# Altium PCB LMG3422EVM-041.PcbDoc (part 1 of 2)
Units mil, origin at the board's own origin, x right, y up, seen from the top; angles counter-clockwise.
Board outline 3001 x 1535.46 mil, 4 copper layers (Top Layer, MidLayer1, MidLayer2, Bottom Layer), stack 46.2 mil thick; 103 components, 73 nets, 350 pads, 858 vias.
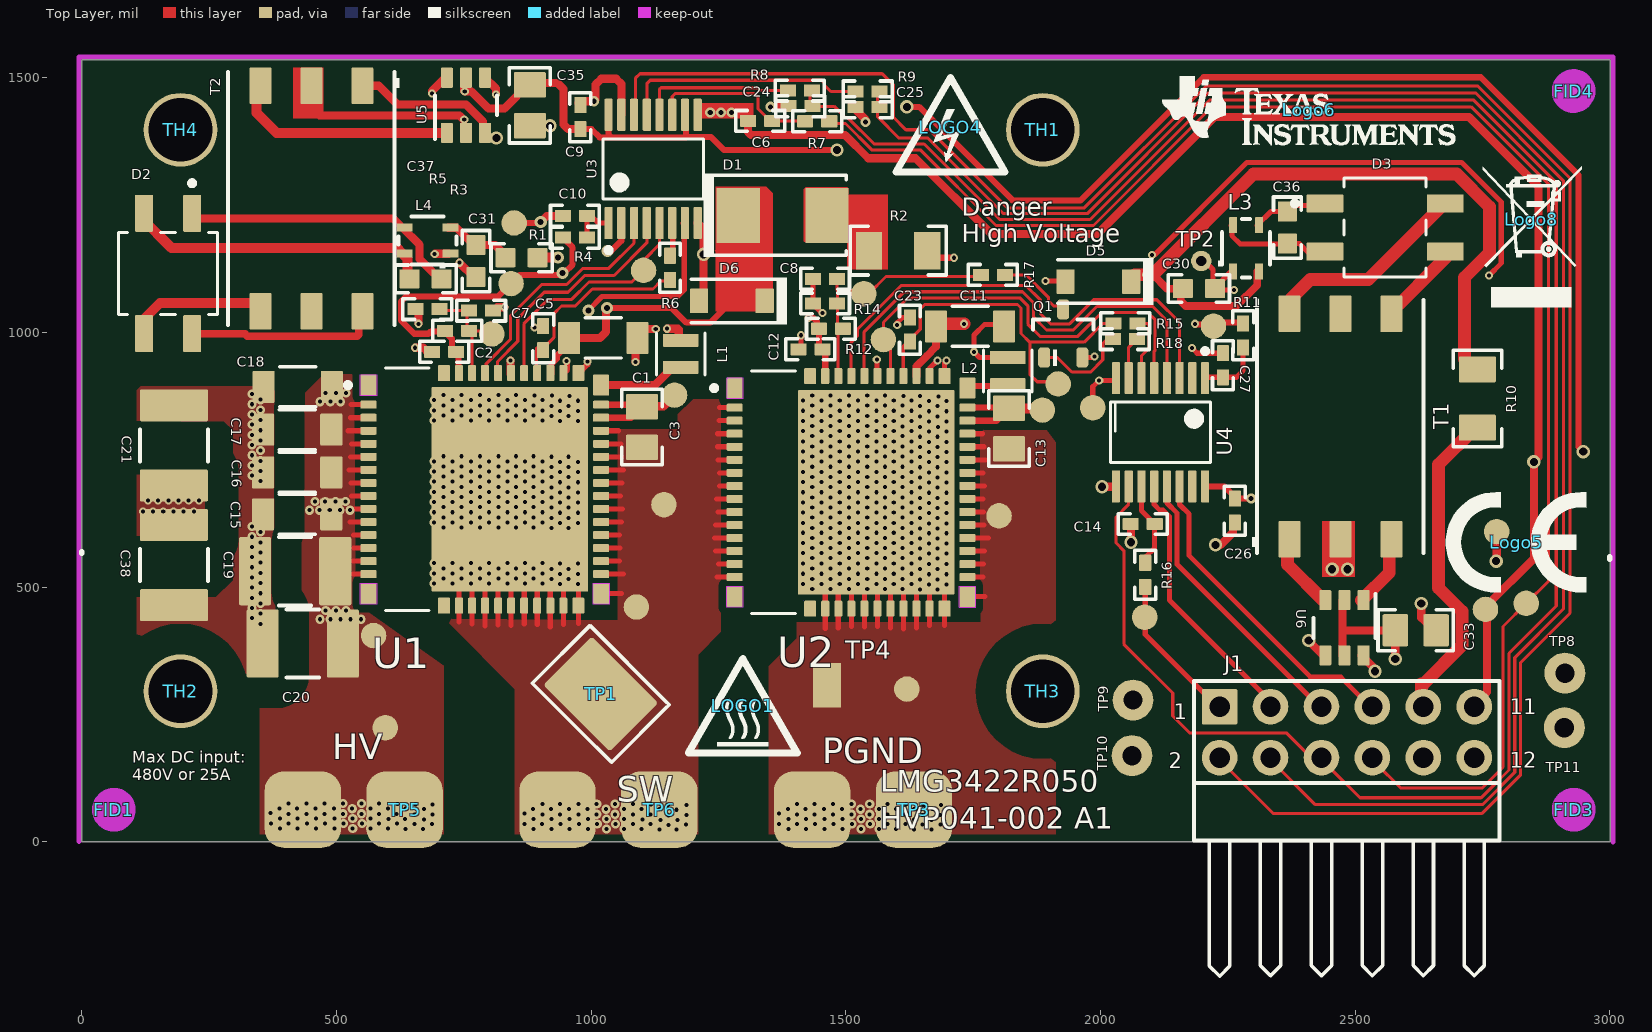
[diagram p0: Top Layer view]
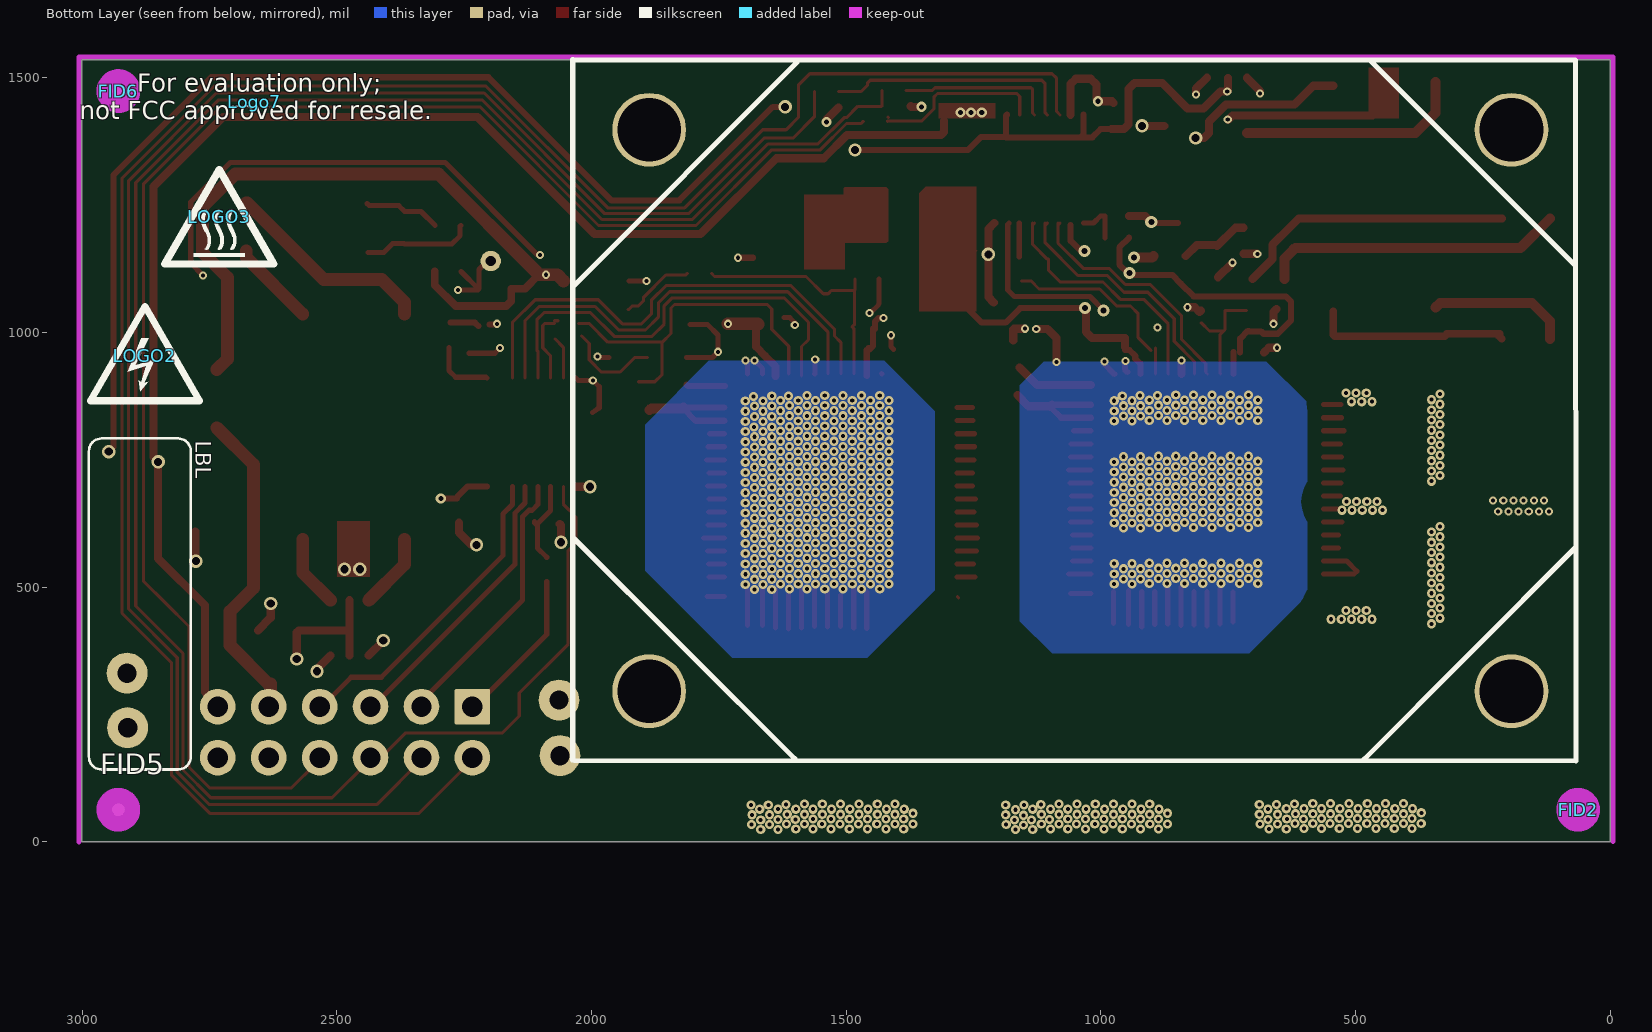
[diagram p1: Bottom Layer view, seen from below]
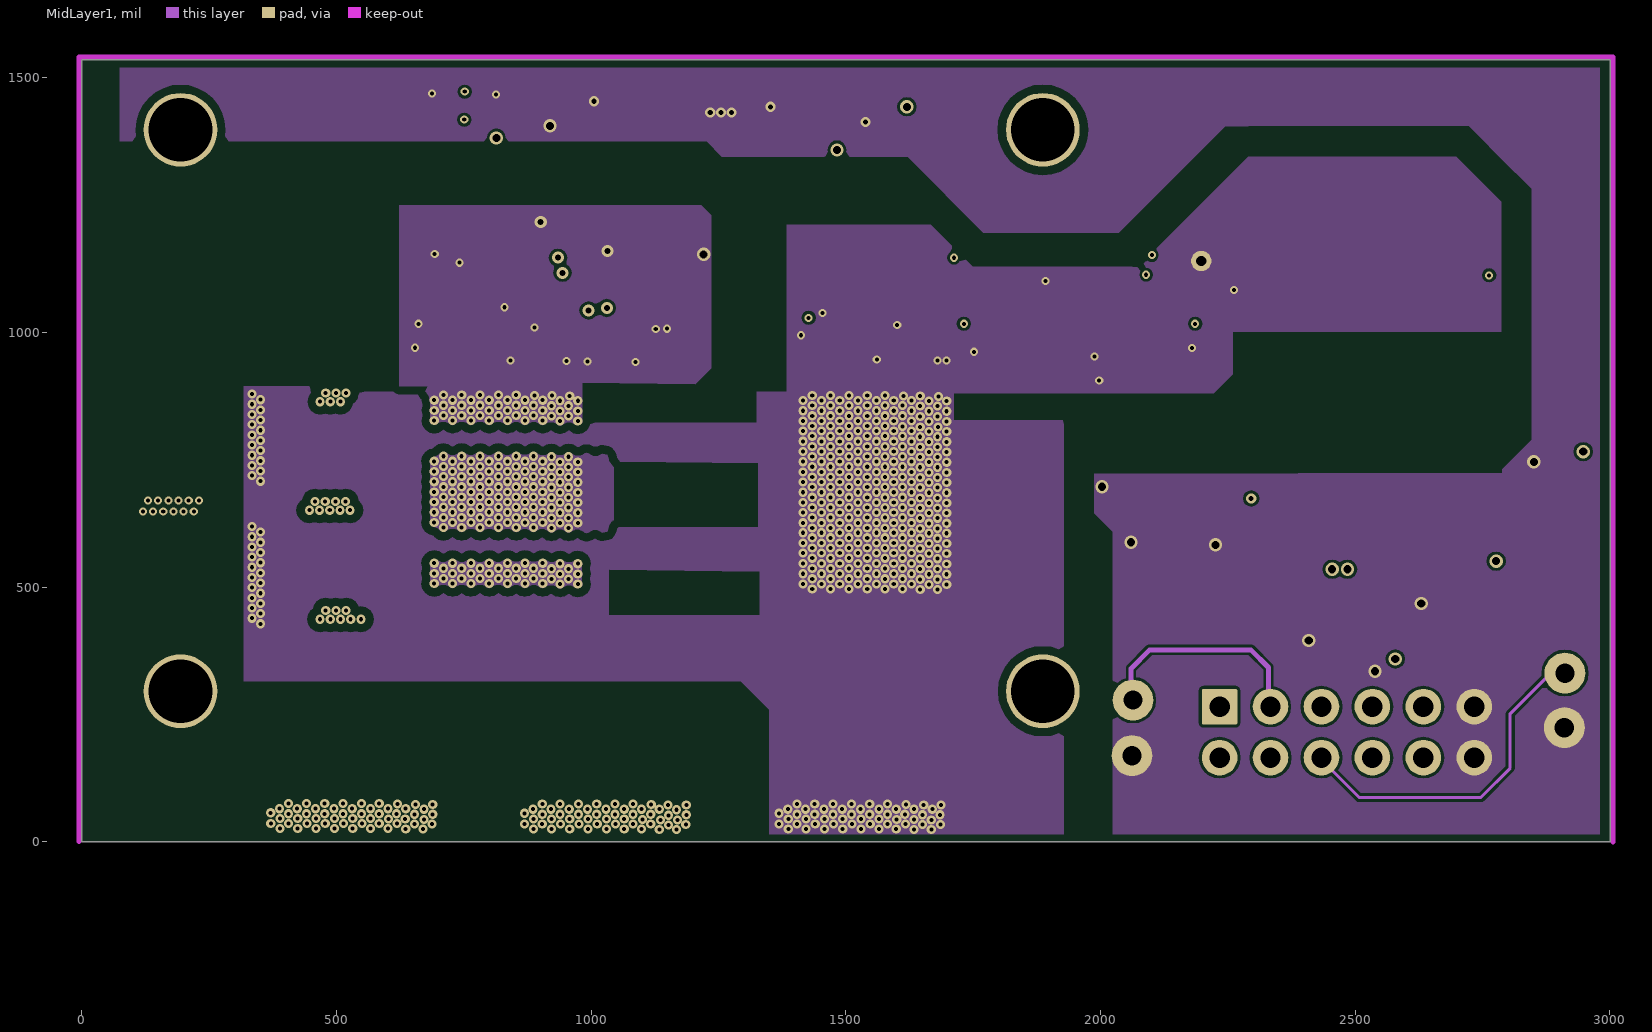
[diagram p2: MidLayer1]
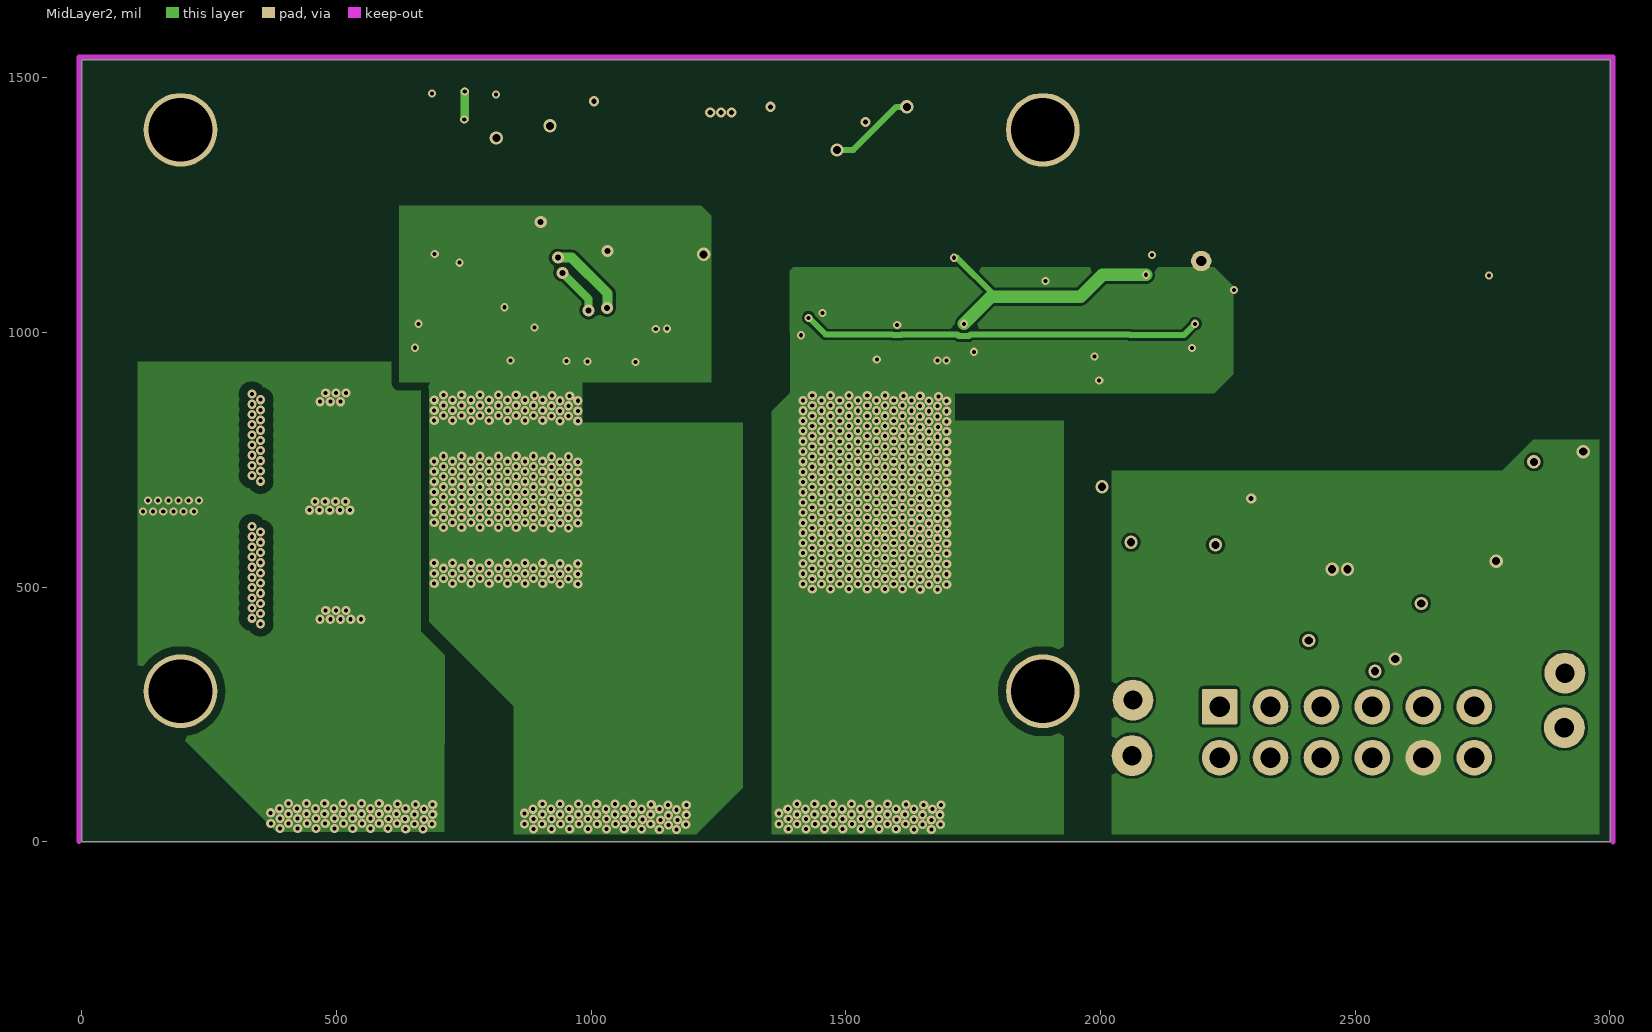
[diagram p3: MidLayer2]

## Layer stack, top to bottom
Top Solder: solder mask 0.4, Solder Resist, Dk 3.5
Top Layer: signal copper 2.8
Dielectric1: core 4.6, FR-4 High Tg, Dk 4.8
MidLayer1: signal copper 2.8
Dielectric2: prepreg 25.8, FR-4 High Tg, Dk 4.8
MidLayer2: signal copper 2.8
Dielectric3: core 4.6, FR-4 High Tg, Dk 4.8
Bottom Layer: signal copper 2.8
Bottom Solder: solder mask 0.4, Solder Resist, Dk 3.5

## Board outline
0,1535.46 3001,1535.46 3001,0 0,0
cut-out: 30,1685

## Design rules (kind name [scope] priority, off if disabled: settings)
AcuteAngle [All] p1: minimum=4.50000000000000E+0001 checktracksonly=FALSE
AssemblyTestPointUsage [All] p1: valid=2
BoardOutlineClearance [OnCopper] p1: gap=15 ignorepadtopadclearanceinfootprint=FALSE
Clearance Clearance_1 [Keepout vs InNet('SW') or InNet('HVBUS') or InNet('PGND')] p1: gap=16 ignorepadtopadclearanceinfootprint=FALSE
Clearance Clearance_VSW_Mid1 [(OnMultiLayer Or OnMid) And InNetClass('VSWNET') vs OnMid And Not InNetClass('VSWNET')] p2: gap=16 ignorepadtopadclearanceinfootprint=TRUE
Clearance Clearance_VSW_Mid2 [(OnMultiLayer Or OnMid) And Not InNetClass('VSWNET') vs OnMid And InNetClass('VSWNET')] p3: gap=16 ignorepadtopadclearanceinfootprint=TRUE
Clearance Clearance_VSW [InNetClass('VSWNET')   and OnCopper vs Not InNetClass('VSWNET')     and OnCopper] p4: gap=60 ignorepadtopadclearanceinfootprint=TRUE
Clearance Clearance_VHV_Mid1 [(OnMultiLayer Or OnMid) And InNetClass('VHV') vs OnMid And Not InNetClass('VHV')] p5: gap=16 ignorepadtopadclearanceinfootprint=TRUE
Clearance Clearance_VHV_Mid2 [(OnMultiLayer Or OnMid) And Not InNetClass('VHV') vs OnMid And InNetClass('VHV')] p6: gap=16 ignorepadtopadclearanceinfootprint=TRUE
Clearance Clearance_VHV [InNetClass('VHV') vs Not InNetClass('VHV')] p7: gap=60 ignorepadtopadclearanceinfootprint=FALSE
Clearance Clearance_INGND [InNetClass('INGND') and OnCopper vs Not InNetClass('INGND')  and OnCopper] p8: gap=60 ignorepadtopadclearanceinfootprint=FALSE
Clearance [All] p9: gap=5.5 ignorepadtopadclearanceinfootprint=FALSE
ComponentClearance ComponentClearance_Shunt [InComponentClass('Header') vs InComponentClass('Shunt')] p1 off: gap=0 collisioncheckmode=3 verticalgap=0 showdistances=FALSE
ComponentClearance ComponentClearance_MountingHoles_FiducialMarks [InComponentClass('Mounting Holes') vs InComponentClass('FiducialMark')] p2 off: gap=50 collisioncheckmode=3 verticalgap=10 showdistances=FALSE
ComponentClearance ComponentClearance_Logo [InComponentClass('Logo')] p3 off: gap=0 collisioncheckmode=3 verticalgap=10 showdistances=FALSE
ComponentClearance ComponentClearance_ScrewToNut [(HasFootprint('NY PMS 440 0025 PH')) vs (HasFootprint('Keystone_1902C'))] p4 off: gap=5 collisioncheckmode=3 verticalgap=10 showdistances=FALSE
ComponentClearance ComponentClearance_MountingHoles [InComponentClass('Mounting Holes')] p5 off: gap=250 collisioncheckmode=3 verticalgap=100000 showdistances=FALSE
ComponentClearance ComponentClearance_SmallPassives [HasFootprint('0201*') or HasFootprint('0402*') or HasFootprint('0508') or HasFootprint('0603*') or HasFootprint('0612') or HasFootprint('0805*') or HasFootprint('0815*') or HasFootprint('0830*') or HasFootprint('1206*') or HasFootprint('1210*') or HasFootprint('1808*') or HasFootprint('1812*') or HasFootprint('1825*') or HasFootprint('2010*') or HasFootprint('2220*') or HasFootprint('2225*') or HasFootprint('2512*') or HasFootprint('2728*') or HasFootprint('3518*') vs HasFootprint('0201*') or HasFootprint('0402*') or HasFootprint('0508') or HasFootprint('0603*') or HasFootprint('0612') or HasFootprint('0805*') or HasFootprint('0815*') or HasFootprint('0830*') or HasFootprint('1206*') or HasFootprint('1210*') or HasFootprint('1808*') or HasFootprint('1812*') or HasFootprint('1825*') or HasFootprint('2010*') or HasFootprint('2220*') or HasFootprint('2225*') or HasFootprint('2512*') or HasFootprint('2728*') or HasFootprint('3518*')] p6 off: gap=15 collisioncheckmode=3 verticalgap=10 showdistances=FALSE
ComponentClearance ComponentClearance_THtoSMT [IsThruComponent vs IsSMTComponent] p7 off: gap=30 collisioncheckmode=3 verticalgap=30 showdistances=FALSE
ComponentClearance ComponentClearance_THtoTH [IsThruComponent vs IsThruComponent] p8 off: gap=74 collisioncheckmode=3 verticalgap=30 showdistances=FALSE
ComponentClearance [All] p9 off: gap=15 collisioncheckmode=3 verticalgap=10 showdistances=FALSE
DiffPairsRouting [All] p1: maxlimit=100 minlimit=10 mostfreqgap=10 toplayer_minwidth=15 toplayer_maxwidth=15 toplayer_prefwidth=15 midlayer1_minwidth=15 midlayer1_maxwidth=15 midlayer1_prefwidth=15 midlayer2_minwidth=15 midlayer2_maxwidth=15 midlayer2_prefwidth=15 bottomlayer_minwidth=15 bottomlayer_maxwidth=15 bottomlayer_prefwidth=15 maxuncoupledlength=1000
FabricationTestPointUsage TestPointUsage [All] p1: valid=2 allowmultiple=FALSE
FabricationTestpoint Testpoint [All] p1: side=3 testpointundercomponent=TRUE minsize=40 maxsize=100 preferedsize=60 minholesize=0 maxholesize=40 preferedholesize=32 testpointgrid=1 allowsidetop=TRUE allowsidebottom=TRUE usegrid=TRUE gridtolerance=0.01
FanoutControl Fanout_LCC [IsLCC] p1: bgadir=Out bgaviamode=Centered fanoutstyle=Auto fanoutdirection=Alternating viagrid=1 // Fanout_LCC (Default Rule)
FanoutControl Fanout_BGA [IsBGA] p2: bgadir=Out bgaviamode=Centered fanoutstyle=Auto fanoutdirection=Alternating viagrid=1 // Fanout_BGA (Default Rule)
FanoutControl Fanout_Default [All] p4: bgadir=Out bgaviamode=Centered fanoutstyle=Auto fanoutdirection=Alternating viagrid=1 // Fanout_Default (Default Rule)
FanoutControl Fanout_Small [(CompPinCount < 5)] p5: bgadir=Out bgaviamode=Centered fanoutstyle=Auto fanoutdirection=OutThenIn viagrid=1 // Fanout_Small (Default Rule)
Height [All] p1 off: minheight=0 maxheight=1000 prefheight=500
HoleSize [All] p1: absolutevalues=TRUE maxlimit=251 minlimit=6 maxpercent=80.000 minpercent=20.000
MinimumAnnularRing MinimumAnnularRing_ThermalPadVias [IsVia and InAnyComponent] p1 off: minimumring=5
MinimumAnnularRing [IsVia] p2 off: minimumring=5
MinimumSolderMaskSliver MinimumSolderMaskSliver_Logo [InComponentClass('Logo') vs InComponentClass('Logo')] p1: minsoldermaskwidth=0.7
MinimumSolderMaskSliver [All] p2: minsoldermaskwidth=3.94
PlaneConnect [All] p1: planeconnectstyle=Relief reliefexpansion=10 reliefentries=4 reliefconductorwidth=10 reliefairgap=10
PolygonConnect [All] p1: connectstyle=Direct reliefconductorwidth=10 reliefentries=4 polygonreliefangle="90 Angle" airgapwidth=10
RoomDefinition HVP041-002_A1_DC [InComponentClass('HVP041-002_A1_DC')] p1: confinementstyle=ConfineIn formatcopy=TRUE lockcomponents=FALSE outline -767,-2072.28 1233,-2072.28 1233,-1072.28 -767,-1072.28
RoomDefinition HVP041-002_A1_Hardware [InComponentClass('HVP041-002_A1_Hardware')] p2: confinementstyle=ConfineIn formatcopy=TRUE lockcomponents=FALSE outline 3046,55.72 3361,55.72 3361,201.72 3046,201.72
RoutingVias ThermalPadVias [IsVia and InAnyComponent] p1: holewidth=7.87 width=19.68 viastyle="Through Hole" minholewidth=7.87 minwidth=19.68 maxholewidth=12.99 maxwidth=23.62
RoutingVias [All] p2: holewidth=10 width=20 viastyle="Through Hole" minholewidth=6 minwidth=10 maxholewidth=40 maxwidth=65
SMDToCorner [All] p1: distance=30000
SilkToSilkClearance [All] p1: silktosilkclearance=0
SilkToSolderMaskClearance SilkscreenOverComponentPads [IsPad] p1: minsilkscreentomaskgap=5 clearancetoexposedcopper=TRUE
SolderMaskExpansion [All] p1: expansion=1.97
Width [All] p1: maxlimit=1000 minlimit=6 preferedwidth=10 checkconnectedcopper=TRUE
15 further rules are at their usual default settings.

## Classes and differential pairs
net class PGND: 5V_L 12V Bot_FET_FAULT FAULT_L IN_L INA ISO_12V_L ISO_12V_L_B ISO_RET_L_B NetC8_1 NetC27_1 NetD3_3 NetD3_4 NetL2_2 NetQ1_1 NetQ1_3 NetR15_1 NetR18_1 OC_L PGND TEMP_L Top_FET_FAULT U2NC17 U2NC54 VNEG_L
net class INGND: 5V 12V AGND Bot_FET_FAULT Bot_FET_OC Bot_FET_PWM Bot_FET_TEMP NetC6_1 NetC14_2 NetR8_2 NetR9_2 NetT1_1 NetT1_3 NetT2_1 NetT2_3 OUTA Top_FET_FAULT Top_FET_OC Top_FET_PWM Top_FET_TEMP
component class HVP041-002_A1_Hardware: !PCB1 FID1 FID2 FID3 FID4 FID5 FID6 H2 H3 H4 H5 H6 LBL LOGO1 LOGO2 LOGO3 LOGO4 Logo5 Logo6 Logo7 Logo8 ZZ2 ZZ3 ZZ4
component class HVP041-002_A1_DC: C1 C2 C3 C5 C6 C7 C8 C9 C10 C11 C12 C13 C14 C15 C16 C17 C18 C19 C20 C21 C23 C24 C25 C26 C27 C30 C31 C33 C35 C36 C37 C38 D1 D2 D3 D5 D6 HV J1 L1 L2 L3 L4 PGND Q1 R1 R2 R3 R4 R5 R6 R7 R8 R9 R10 R11 R12 R14 R15 R16 R17 R18 SW T1 T2 TH1 TH2 TH3 TH4 TP1 TP2 TP3 TP4 TP5 TP6 TP8 TP9 TP10 TP11 U1 U2 U3 U4 U5 U6
net class VSWNET: 5V_H FAULT_H IN_H ISO_12V_H ISO_12V_H_B ISO_RET_H_B ISONC2 NC1 NC2 NC3 NC4 NetC1_1 NetC10_1 NetD2_3 NetD2_4 NetL1_2 NetR6_1 OC_H RDRV_H SW TEMP_H U1NC17 U1NC54 U2NC1 U2NC16 VNEG_H
net class VHV: HVBUS U1NC1 U1NC16

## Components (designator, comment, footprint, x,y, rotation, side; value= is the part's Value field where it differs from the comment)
C1 "C1206C106K3RACTU" 1206_190 1024,989.28 r0 top value=10uF
C2 "CL05B224KO5NNNC" 0402#1 711.62,962 r180 top value=0.22uF
C3 "GRM219R61E225KA12D" 0805_HV 1100,814.28 r270 top value=2.2uF
C5 "C1005C0G1H220J050BA" 0402#1 906.01,988.82 r270 top value=22pF
C6 "C1005C0G1H680J050BA" 0402#1 1332,1415.28 r180 top value=68pF
C7 "04025A101FAT2A" 0402#2 784,1043 r0 top value=100pF
C8 "04025A101FAT2A" 0402#2 1459.38,1105.27 r180 top value=100pF
C9 "C1005X5R1E105K050BC" 0402#1 979,1422.77 r90 top value=1uF
C10 "C1005X7R1H104K050BB" 0402#1 968.38,1229 r180 top value=0.1uF
C11 "C1206C106K3RACTU" 1206_190 1744,1012 r180 top value=10uF
C12 "CL05B224KO5NNNC" 0402#1 1430.62,967 r180 top value=0.22uF
C13 "GRM219R61E225KA12D" 0805_HV 1820.54,811.28 r270 top value=2.2uF
C14 "C1005C0G1H680J050BA" 0402#1 2083.04,624 r0 top value=68pF
C15 "C1206C223KDRACTU" 1206_190 423,642.89 r180 top value=0.022uF
C16 "C1206C223KDRACTU" 1206_190 423,725.28 r180 top value=0.022uF
C17 "C1206C223KDRACTU" 1206_190 423,809.28 r180 top value=0.022uF
C18 "C1206C223KDRACTU" 1206_190 424,893.28 r180 top value=0.022uF
C19 "C1812W104KDRACTU" 1812_254 419,531.28 r180 top value=0.1uF
C20 "C1812W104KDRACTU" 1812_254 434,389.28 r180 top value=0.1uF
C21 "C1812W104KDRACTU" 1812_254 181,778.28 r90 top value=0.1uF
C23 "C1005C0G1H220J050BA" 0402#1 1626,1005.65 r270 top value=22pF
C24 "C1005C0G1H680J050BA" 0402#2 1411,1444.35 r180 top value=68pF
C25 "C1005C0G1H680J050BA" 0402#2 1543,1442.28 r180 top value=68pF
C26 "C1005X5R1E105K050BC" 0402#1 2264,650.28 r270 top value=1uF
C27 "C1005X7R1H104K050BB" 0402#1 2240.5,935.62 r90 top value=0.1uF
C30 "C1608X5R1V475K080AC" 0603 2193.5,1086.28 r0 top value=4.7uF
C31 "C1608X5R1V475K080AC" 0603 774,1140.28 r270 top value=4.7uF
C33 "GCM21BR71C475KA73L" 0805_HV 2619,415.28 r0 top value=4.7uF
C35 "GCM21BR71C475KA73L" 0805_HV 879.73,1445.99 r270 top value=4.7uF
C36 "C1608X5R1V475K080AC" 0603 2367,1206 r270 top value=4.7uF
C37 "C1608X5R1V475K080AC" 0603 675,1105.28 r180 top value=4.7uF
C38 "C1812W104KDRACTU" 1812_254 181,543.28 r270 top value=0.1uF
D1 "GB01SLT06-214" SMB 1376,1230 r0 top value=650V
D2 "KMB23STR" FP-KMB23STR_SMT_4MM725_3MM85-MFG 169.55,1115.83 r270 top
D3 "KMB23STR" FP-KMB23STR_SMT_4MM725_3MM85-MFG 2559,1206 r0 top
D5 "BZT52C16-7-F" SOD-123 1996,1099.87 r180 top value=16V
D6 "BZT52C16-7-F" SOD-123 1276.47,1062 r180 top value=16V
FID1 "Fiducial" Fiducial6.4-20 63,63 r90 top
FID2 "Fiducial" Fiducial6.4-20 63,63 r180 bottom
FID3 "Fiducial" Fiducial6.4-20 2929,63 r90 top
FID4 "Fiducial" Fiducial6.4-20 2929,1474 r90 top
FID5 "Fiducial" Fiducial6.4-20 2929,63 r180 bottom
FID6 "Fiducial" Fiducial6.4-20 2929,1474 r180 bottom
HV "3621-0-32-15-00-00-08-0" MILL-MAX_3621-0-32-XX-00-00-08-0 434,-30.72 r0 top
J1 "TSW-106-08-G-D-RA" AB12-DEST 2484,215.28 r0 top
L1 "SDEM20161T-4R7MS" FP-SDEM20161T-4R7MS_SMD2-MFG#1 1176,957.98 r270 top
L2 "SDEM20161T-4R7MS" FP-SDEM20161T-4R7MS_SMD2-MFG#2 1818,924.28 r270 top
L3 "ACM2520-601-2P-T002" TDK_ACM2520-2P 2286,1165.28 r90 top
L4 "ACM2520-601-2P-T002" TDK_ACM2520-2P 679,1180.28 r180 top
LBL "THT-14-423-10" Label_650x200 2887,467 r90 bottom
LOGO1 "CAUTION HOT SURFACE" IEC_HotSurface_Small 1298,267 r0 top
LOGO2 "DANGER HIGH VOLTAGE" IEC_HighVoltage_Small 2877,954 r180 bottom
LOGO3 "CAUTION HOT SURFACE" IEC_HotSurface_Small 2731.01,1227.53 r180 bottom
LOGO4 "DANGER HIGH VOLTAGE" IEC_HighVoltage_Small 1705.53,1403.21 r0 top
Logo5 "CE Mark" CE_Mark_5mm 2816,588 r0 top
Logo6 "Texas Instruments" TI_Stacked_Overlay_Small_Vertical 2409,1437 r270 top
Logo7 "FCC disclaimer" FCC_disclaimer_stacked 2662.67,1453.39 r180 bottom
Logo8 "WEEE logo" WEEE_Minimum 2846,1222 r0 top
PGND "3621-0-32-15-00-00-08-0" MILL-MAX_3621-0-32-XX-00-00-08-0 1434,-30.72 r0 top
Q1 "MGSF1N02LT1G" SOT-23 1927,998 r90 top value=20V
R1 "MCT06030Z0000ZP500" 0603 863.5,1146.73 r0 top value=0
R2 "CRCW12062R05FKEA" 1206#1 1602.91,1160.5 r0 top value=2.05
R3 "MCR01MZPJ000" 0402#1 737,1003.28 r180 top value=0
R4 "MCR01MZPJ000" 0402#2 968.38,1186 r0 top value=0
R5 "CRCW040220K0FKED" 0402#1 678.62,1046 r0 top value=20.0k
R6 "CRCW0402300RJNED" 0402#1 1155,1127 r270 top value=300
R7 "RC0402FR-0749R9L" 0402#1 1444,1414.7 r180 top value=49.9
R8 "CRCW0402300RJNED" 0402#2 1410,1474.91 r180 top value=300
R9 "CRCW0402300RJNED" 0402#2 1543,1473.28 r180 top value=300
R10 "ERJ-8GEY0R00V" 1206#2 2740,870.28 r90 top value=0
R11 "MCR01MZPJ000" 0402#2 2280.25,994.38 r270 top value=0
R12 "MCR01MZPJ000" 0402#1 1471,1007.28 r180 top value=0
R14 "CRCW040220K0FKED" 0402#1 1459.38,1057 r0 top value=20.0k
R15 "CRCW0402300RJNED" 0402#1 2049,1018 r180 top value=300
R16 "RC0402FR-0749R9L" 0402#1 2088,524.23 r90 top value=49.9
R17 "CRCW040220K0FKED" 0402#2 1788.9,1113 r180 top value=20.0k
R18 "CRCW040210R0FKED" 0402#2 2048,987 r180 top value=10.0
SW "3621-0-32-15-00-00-08-0" MILL-MAX_3621-0-32-XX-00-00-08-0 934,-30.72 r0 top
T1 "750315371" Wurth_750315371 2471.24,815.28 r90 top value=105uH
T2 "750315371" Wurth_750315371 451,1263 r270 top value=105uH
TH1 "" TP_H045P075#1 1886.91,1397.91 r90 top
TH2 "" TP_H045P075#1 194,295.55 r90 top
TH3 "" TP_H045P075#1 1886.91,295.55 r90 top
TH4 "" TP_H045P075#2 194,1397.91 r90 top
TP1 "5016" Testpoint_Keystone_Compact 1019,290.24 r135 top
TP2 "" TESTPOINT#1 2198,1140.28 r0 top
TP3 "3621-0-32-15-00-00-08-0" MILL-MAX_3621-0-32-XX-00-00-08-0 1634,-30.72 r0 top locked
TP4 "" Harwin_S2751-46R 1463.41,307.28 r90 top
TP5 "3621-0-32-15-00-00-08-0" MILL-MAX_3621-0-32-XX-00-00-08-0 634,-30.72 r0 top
TP6 "3621-0-32-15-00-00-08-0" MILL-MAX_3621-0-32-XX-00-00-08-0 1134,-30.72 r0 top
TP8 "" TESTPOINT#2 2912,331.28 r0 top
TP9 "" TESTPOINT#2 2064,278.28 r0 top
TP10 "" TESTPOINT#2 2062,169.3 r90 top
TP11 "" TESTPOINT#2 2911,224.22 r90 top
U1 "LMG3422R050RQZT" RQZ0054A-MFG-NV#1 791.35,691.85 r0 top
U2 "LMG3422R050RQZT" RQZ0054A-MFG-NV#2 1510.35,686.02 r0 top
U3 "ISO7741FDBQR" DBQ0016A-MFG 1121.9,1321.08 r90 top
U4 "ISO7762FQDBQRQ1" DBQ0016A-MFG 2118,804 r270 top
U5 "SN6505BDBVR" DBV0006A_N 754.37,1445.99 r90 top
U6 "SN6505BDBVR" DBV0006A_N 2479,420.28 r270 top
ZZ2 "These assemblies are ESD sensitive, ESD precautions shall be observed." AssemblyNote 3482,1786.72 r90 top
ZZ3 "These assemblies must be clean and free from flux and all contaminants. Use of no clean flux is not acceptable." AssemblyNote 3247,415 r90 top
ZZ4 "These assemblies must comply with workmanship standards IPC-A-610 Class 2, unless otherwise specified." AssemblyNote 3127,560.72 r90 top

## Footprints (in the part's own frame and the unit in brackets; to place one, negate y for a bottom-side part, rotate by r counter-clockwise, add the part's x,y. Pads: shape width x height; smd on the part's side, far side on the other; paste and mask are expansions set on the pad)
0402#1 [mm] "0402 from SM-752 data"
  rrect10% 0.8x0.6 smd: 1(-0.6,0) 2(0.6,0)
  silkscreen extent -1.22,-0.52 1.22,0.52, body extent -0.55,-0.3 0.55,0.3, height 0.6
0402#2 [mm] "0402 from SM-752 data"
  rect 0.8x0.6 smd: 1(-0.6,0) 2(0.6,0)
  silkscreen extent -1.22,-0.52 1.22,0.52, body extent -0.55,-0.3 0.55,0.3, height 0.6
0603 [mm] "0603 from SM-752 data"
  rrect10% 1x0.95 smd: 1(-0.8,0) 2(0.8,0)
  silkscreen extent -1.52,-0.69 1.52,0.69, body extent -0.87,-0.47 0.87,0.47, height 1
0805_HV [mil] "0805 with 30mil clearance between pads"
  rrect10% 50x63 smd: 1(-40,0) 2(40,0)
  silkscreen extent -74,-40 74,40, body extent -43,-29 43,29, height 57
1206#1 [mm] "1206 from SM-752 data"
  rect 1.3x1.85 smd: 1(-1.45,0) 2(1.45,0)
  silkscreen extent -2.4,-1.21 2.4,1.21, body extent -1.7,-0.9 1.7,0.9, height 1.35
1206#2 [mm] "1206 from SM-752 data"
  rrect10% 1.3x1.85 smd: 1(-1.45,0) 2(1.45,0)
  silkscreen extent -2.4,-1.21 2.4,1.21, body extent -1.7,-0.9 1.7,0.9, height 1.35
1206_190 [mm] "1206_190"
  rrect10% 1.1x1.6 smd: 1(-1.7,0) 2(1.7,0)
  silkscreen extent -0.9,-1 0.9,1, body extent -1.75,-0.95 1.75,0.95, height 1.9
1812_254 [mm] "SMD, 2-Leads, Body 4.8x3.4mm"
  rrect10% 1.6x3.4 smd: 1(-2,0) 2(2,0)
  silkscreen extent -0.8,-1.7 0.8,1.7, body extent -2.4,-1.7 2.4,1.7, height 2.54
AB12-DEST [mil] "Samtec right angle header, pins flipped from convention"
  rrect10% 70x70 hole 40: 1(-250,50)
  round 70 hole 40: 2(-250,-50) 3(-150,50) 4(-150,-50) 5(-50,50) 6(-50,-50) 7(50,50) 8(50,-50) 9(150,50) 10(150,-50) 11(250,50) 12(250,-50)
  silkscreen extent -300,-479 300,100, body extent -300,-440 300,63, height 219
AssemblyNote [mil] "Assembly Note"
CE_Mark_5mm [mil] "Minimum text height for CE Mark"
  silkscreen extent -138,-98 138,98
DBQ0016A-MFG [mm]
  rrect24% 1.6x0.41 smd paste+0 mask+0: 1(-2.7,2.222) 2(-2.7,1.587) 3(-2.7,0.952) 4(-2.7,0.317) 5(-2.7,-0.318) 6(-2.7,-0.953) 7(-2.7,-1.588) 8(-2.7,-2.223) 9(2.7,-2.223) 10(2.7,-1.588) 11(2.7,-0.953) 12(2.7,-0.318) 13(2.7,0.317) 14(2.7,0.952) 15(2.7,1.587) 16(2.7,2.222)
  silkscreen extent -4.17,-2.5 1.5,2.5, body extent -3.6,-2.75 3.6,2.75, height 0.25
DBV0006A_N [mm] "SOT23, 6-Leads, Body 2.9x1.6mm, Pitch 0.95mm, Lead Span 2.8mm, IPC Medium Density"
  rrect17% 1x0.6 smd: 1(-1.375,0.95) 2(-1.375,0) 3(-1.375,-0.95) 4(1.375,-0.95) 5(1.375,0) 6(1.375,0.95)
  silkscreen extent -1.67,-1.55 0.5,1.55, body extent -1.42,-1.46 1.42,1.46, height 1.12
FCC_disclaimer_stacked [mil]
Fiducial6.4-20 [mil]
  round 25 smd mask+26.87: 1(0,0)
  Top Layer keep-out circle w46.37: c0,0 r19.68
FP-KMB23STR_SMT_4MM725_3MM85-MFG [mm]
  rrect11% 1.84x0.9 smd paste+0 mask+0: 1(-3,1.2) 2(-3,-1.2) 3(3,-1.2) 4(3,1.2)
  silkscreen extent -4.62,-2.47 2.05,2.47, body extent -3.5,-2.36 3.5,2.36, height 3
FP-SDEM20161T-4R7MS_SMD2-MFG#1 [mm]
  rrect15% 0.65x1.778 smd paste+0 mask+0: 1(-0.675,0) 2(0.675,0)
  silkscreen extent -1.05,-1.22 1.05,1.2, body extent -1.15,-0.95 1.15,0.95, height 0.25
FP-SDEM20161T-4R7MS_SMD2-MFG#2 [mm]
  rrect10% 0.65x1.778 smd paste+0 mask+0: 1(-0.675,0)
  rrect15% 0.65x1.778 smd paste+0 mask+0: 2(0.675,0)
  silkscreen extent -1.05,-1.22 1.05,1.2, body extent -1.15,-0.95 1.15,0.95, height 0.25
Harwin_S2751-46R [mm] "Test Point, SMT"
  rect 2.2x1.4 smd: 1(0,0)
  body extent -1,-0.6 1,0.6, height 1.4
IEC_HighVoltage_Small [mil]
  silkscreen extent -107,-88 107,97
IEC_HotSurface_Small [mil]
  silkscreen extent -107,-93 107,92
Label_650x200 [mil] "Thermal Transfer Label"
  round 1 on Mech14: 0(0,0)
  silkscreen extent -325,-100 325,100, body extent -325,-100 325,100, height 1
MILL-MAX_3621-0-32-XX-00-00-08-0 [mil]
  rrect50% 150x150 smd: 1(0,94)
  body extent -62,-199 62,157, height 62
RQZ0054A-MFG-NV#1 [mm]
  rrect13% 0.8x1.05 smd paste+0: 1(-5.8,5.2) 16(-5.8,-5.2) 28(5.8,-5.2) 43(5.8,5.2)
  rrect25% 0.8x0.4 smd paste+0 mask+0: 2(-5.8,4.225) 3(-5.8,3.575) 4(-5.8,2.925) 5(-5.8,2.275) 6(-5.8,1.625) 7(-5.8,0.975) 8(-5.8,0.325) 9(-5.8,-0.325) 10(-5.8,-0.975) 11(-5.8,-1.625) 12(-5.8,-2.275) 13(-5.8,-2.925) 14(-5.8,-3.575) 15(-5.8,-4.225) 29(5.8,-4.225) 30(5.8,-3.575) 31(5.8,-2.925) 32(5.8,-2.275) 33(5.8,-1.625) 34(5.8,-0.975) 35(5.8,-0.325) 36(5.8,0.325) 37(5.8,0.975) 38(5.8,1.625) 39(5.8,2.275) 40(5.8,2.925)
  rrect17% 0.6x0.8 smd paste+0: 17(-2.035,-5.8) 27(4.665,-5.8) 44(4.665,5.8) 54(-2.035,5.8)
  rrect25% 0.4x0.8 smd paste+0: 18(-1.285,-5.8) 19(-0.635,-5.8) 20(0.015,-5.8) 21(0.665,-5.8) 22(1.315,-5.8) 23(1.965,-5.8) 24(2.615,-5.8) 25(3.265,-5.8) 26(3.915,-5.8) 45(3.915,5.8) 46(3.265,5.8) 47(2.615,5.8) 48(1.965,5.8) 49(1.315,5.8) 50(0.665,5.8) 51(0.015,5.8) 52(-0.635,5.8) 53(-1.285,5.8)
  rrect25% 0.8x0.4 smd paste+0: 41(5.8,3.575) 42(5.8,4.225)
  rrect1% 7.8x10.2 smd paste-1000 mask+0: 55(1.25,0)
  silkscreen extent -6.95,-6.05 -2.78,6.05, body extent -6.3,-6.3 6.3,6.3, height 0.25
RQZ0054A-MFG-NV#2 [mm]
  rrect13% 0.8x1.05 smd paste+0: 1(-5.8,5.2) 16(-5.8,-5.2) 28(5.8,-5.2) 43(5.8,5.2)
  rrect25% 0.8x0.4 smd paste+0 mask+0: 2(-5.8,4.225) 3(-5.8,3.575) 4(-5.8,2.925) 5(-5.8,2.275) 6(-5.8,1.625) 7(-5.8,0.975) 8(-5.8,0.325) 9(-5.8,-0.325) 10(-5.8,-0.975) 11(-5.8,-1.625) 12(-5.8,-2.275) 13(-5.8,-2.925) 14(-5.8,-3.575) 15(-5.8,-4.225) 29(5.8,-4.225) 30(5.8,-3.575) 31(5.8,-2.925) 32(5.8,-2.275) 33(5.8,-1.625) 34(5.8,-0.975) 35(5.8,-0.325) 36(5.8,0.325) 37(5.8,0.975) 38(5.8,1.625) 39(5.8,2.275) 40(5.8,2.925)
  rrect17% 0.6x0.8 smd paste+0: 17(-2.035,-5.8) 27(4.665,-5.8)
  rrect25% 0.4x0.8 smd paste+0: 18(-1.285,-5.8) 19(-0.635,-5.8) 20(0.015,-5.8) 21(0.665,-5.8) 22(1.315,-5.8) 23(1.965,-5.8) 24(2.615,-5.8) 25(3.265,-5.8) 26(3.915,-5.8)
  rrect25% 0.8x0.4 smd: 41(5.8,3.575) 42(5.8,4.225)
  rrect17% 0.6x0.8 smd paste+0 mask+0.05: 44(4.665,5.8) 54(-2.035,5.8)
  rrect25% 0.4x0.8 smd paste+0 mask+0.05: 45(3.915,5.8) 46(3.265,5.8) 47(2.615,5.8) 48(1.965,5.8) 49(1.315,5.8) 50(0.665,5.8) 51(0.015,5.8) 52(-0.635,5.8) 53(-1.285,5.8)
  rrect1% 7.8x10.2 smd paste-1000 mask+0: 55(1.25,0)
  silkscreen extent -6.95,-6.05 -2.78,6.05, body extent -6.3,-6.3 6.3,6.3, height 0.25
SMB [mil] "Molded Diode, 2-Leads, Body 5.4x3.6mm, IPC Medium Density, based on OnSemi component dimensions"
  rect 85x107.99 smd: 1(-87.01,0) 2(87.01,0)
  silkscreen extent -155,-82 125,82, body extent -106,-71 106,71, height 91
SOD-123 [mm] "On Semi recommended land pattern"
  rrect10% 0.915x1.22 smd: 1(-1.637,0) 2(1.637,0)
  silkscreen extent -2.74,-1.17 2.03,1.17, body extent -1.93,-0.9 1.93,0.9, height 1.35
SOT-23 [mm] "SOT23, 3-Leads, Body 2.9x1.3mm, Pitch 0.95mm, Lead Span 2.5mm, IPC Medium Density"
  rrect50% 1x0.6 smd: 1(-1.2,0.95) 2(-1.2,-0.95) 3(1.2,0)
  silkscreen extent -1.62,-1.5 0.7,1.5, body extent -1.16,-1.45 1.21,1.45, height 1
TDK_ACM2520-2P [mm] "SMD, 4-Leads, Body 2.5x2mm"
  rrect10% 0.8x0.4 smd: 1(-1.15,0.65) 2(-1.15,-0.65) 3(1.15,-0.65) 4(1.15,0.65)
  silkscreen extent -1.45,-1.2 1.45,1.4, body extent -1.35,-1.1 1.35,1.1, height 1.3
TESTPOINT#1 [mil]
  round 40 hole 20: 1(0,0)
TESTPOINT#2 [mil]
  round 80 hole 37.99: 1(0,0)
Testpoint_Keystone_Compact [mil] "Compact SMT test point"
  rrect10% 185x135 smd: 1(0,0)
  silkscreen extent -110,-80 110,80, body extent -75,-56 75,56, height 91
TI_Stacked_Overlay_Small_Vertical [mil]
  silkscreen extent -66,-288 69,288
TP_H045P075#1 [mm] "TP_H0.45P0.75"
  round 3.675 hole 3.175: 1(0,0)
TP_H045P075#2 [mm] "TP_H0.45P0.75"
  round 3.675 hole 3.175 paste+0: 1(0,0)
WEEE_Minimum [mil] "WEEElie bin"
  silkscreen extent -95,-172 99,104
Wurth_750315371 [mm] "SMD, Body 12.6x8.3mm, Pitch 2.54mm"
  rrect10% 1.83x1.09 smd: 1(-5.62,2.54) 2(-5.62,0) 3(-5.62,-2.54) 4(5.62,-2.54) 5(5.62,0) 6(5.62,2.54)
  silkscreen extent -6.3,-4.15 6.3,4.4, body extent -6.35,-4.2 6.35,4.2, height 4.11

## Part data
C1 C11: library part CMP-0008589-2, "CAP, CERM, 10 uF, 25 V, +/- 10%, X7R, 1206_190", Cap_Case=1206, Manufacturer=Kemet, Supplier Part Number 1=399-7442-1-ND, TempCo=X7R, Tolerance_%=10%, Value1=Unknown, Value2=25V, ValueDisplayed=10uF
C2 C12: library part CMP-0860563-1, "CAP, CERM, 0.22 µF, 16 V,+/- 10%, X7R, 0402", Cap_Case=0402, Manufacturer="Samsung Electro-Mechanics", TempCo=X7R, Tolerance_%=10%, Value2=16V, ValueDisplayed=0.22µF
C3 C13: library part CMP-0008208-1, "CAP, CERM, 2.2 uF, 25 V, +/- 10%, X5R, 0805", Cap_Case=0805, Manufacturer=MuRata, Supplier Part Number 1=490-1701-1-ND, TempCo=X5R, Tolerance_%=10%, Value1="0.006 ohm", Value2=25V, ValueDisplayed=2.2uF
C5 C23: library part CMP-0006248-2, "CAP, CERM, 22 pF, 50 V, +/- 5%, C0G/NP0, 0402", Alternate Manufacturer=TDK, Alternate PartNumber=CGA2B2NP01H220J050BA, Cap_Case=0402, Supplier Part Number 1=445-1239-1-ND, TempCo=C0G/NP0, Tolerance_%=5%, Value1=Unknown, Value2=50V, ValueDisplayed=22pF
C6 C14 C24 C25: library part CMP-0006251-2, "CAP, CERM, 68 pF, 50 V, +/- 5%, C0G/NP0, 0402", Alternate Manufacturer=Murata, Alternate PartNumber=GRM1555C1H680JA01D, Cap_Case=0402, Manufacturer=TDK, Supplier Part Number 1=445-1245-1-ND, TempCo=C0G/NP0, Tolerance_%=5%, Value1=Unknown, Value2=50V, ValueDisplayed=68pF
C7 C8: library part CMP-0006196-2, "CAP, CERM, 100 pF, 50 V, +/- 1%, C0G/NP0, 0402", Cap_Case=0402, Manufacturer=AVX, Supplier Part Number 1=478-3658-1-ND, TempCo=C0G/NP0, Tolerance_%=1%, Value1=Unknown, Value2=50V, ValueDisplayed=100pF
C9 C26: library part CMP-0006276-2, "CAP, CERM, 1 uF, 25 V, +/- 10%, X5R, 0402", Alternate Manufacturer=TDK, Alternate PartNumber=C1005X5R1E225K050BC, Cap_Case=0402, Supplier Part Number 1=445-9066-1-ND, TempCo=X5R, Tolerance_%=10%, Value1=Unknown, Value2=25V, ValueDisplayed=1uF
C10 C27: library part CMP-0006297-2, "CAP, CERM, 0.1 uF, 50 V, +/- 10%, X7R, 0402", Alternate Manufacturer="Wurth Elektronik", Alternate PartNumber=885012205037, Cap_Case=0402, Manufacturer=TDK, Supplier Part Number 1=445-5932-1-ND, TempCo=X7R, Tolerance_%=10%, Value1="0.039064 ohm", Value2=50V, ValueDisplayed=0.1uF
C15 C16 C17 C18: library part CMP-0084048-1, "CAP, CERM, 0.022 µF, 1000 V,+/- 10%, X7R, AEC-Q200 Grade 1, 1206", Cap_Case=1206, Manufacturer=Kemet, TempCo=X7R, Tolerance_%=10%, Value2=1000V, ValueDisplayed=0.022µF
C19 C20 C21 C38: library part CMP-0009326-2, "CAP, CERM, 0.1 uF, 1000 V, +/- 10%, X7R, 1812", Cap_Case=1812, Manufacturer=Kemet, Supplier Part Number 1=399-6523-1-ND, TempCo=X7R, Tolerance_%=10%, Value1=Unknown, Value2=1000V, ValueDisplayed=0.1uF
C30 C31 C36 C37: library part CMP-0007022-5, "CAP, CERM, 4.7 uF, 35 V, +/- 10%, X5R, 0603", Cap_Case=0603, Manufacturer=TDK, Supplier Part Number 1=445-9064-1-ND, TempCo=X5R, Tolerance_%=10%, Value1="0.003728 ohm", Value2=35V, ValueDisplayed=4.7uF
C33 C35: library part CMP-0008020-2, "CAP, CERM, 4.7 uF, 16 V, +/- 10%, X7R, AEC-Q200 Grade 1, 0805", Cap_Case=0805, Manufacturer=MuRata, Supplier Part Number 1=490-5332-1-ND, TempCo=X7R, Tolerance_%=10%, Value1=Unknown, Value2=16V, ValueDisplayed=4.7uF
D1: library part CMP-0076998-2, "Diode, Schottky, 650 V, 1 A, SMB", Manufacturer="GeneSiC Semiconductor", Value1=1A, Value2=2V
D2 D3: library part CMP-0089345-2, "Bridge Rectifier Single Phase Schottky 30V Surface Mount MBS", Digikey Part Number=1655-1883-1-ND, Forward Current=2A, Manufacturer=SMC, Max Surge Forward Current=50A, Operating Temperature Range="-55°C to +150°C", Peak Reverse Current=0.1mA, ValueDisplayed=28pF
D5 D6: library part CMP-0005769-2, "Diode, Zener, 16 V, 500 mW, AEC-Q101, SOD-123", Manufacturer="Diodes Inc.", Power_W=500mW, Supplier Part Number 1=BZT52C16-FDICT-ND, Value1=0.5W
FID1 FID2 FID3 FID4 FID5 FID6: library part CMP-0077181-1, "Fiducial mark.  There is nothing to buy or mount.", Manufacturer=N/A
HV PGND SW TP3 TP5 TP6: library part CMP-0082316-1, Manufacturer=Mill-Max, Supplier Part Number 1=575-3621032150000
J1: library part CMP-0075414-2, "Header, 100mil, 6x2, Gold, R/A, TH", Color=Black, Current_A=6.3A, Manufacturer=Samtec, Supplier Part Number 1=SAM1037-06-ND, Voltage_V=550V
L1 L2: library part CMP-0089347-1, "4.7µH Unshielded Inductor 1.1A 426mOhm Max 0806 (2016 Metric)", Digikey Part Number=2037-SDEM20161T-4R7MSCT-ND, Manufacturer=Cyntec, Operating Temperature Range="-55°C to +125°C", Test Frequency=1MHz, Tolerance_%=20%
L3 L4: library part CMP-0013161-2, "Coupled inductor, 0.2 A, 0.45 ohm, SMD", Manufacturer=TDK, Supplier Part Number 1=445-8930-1-ND
LBL: library part CMP-0003625-1, "Thermal Transfer Printable Labels, 0.650\" W x 0.200\" H - 10,000 per roll", Manufacturer=Brady, Supplier Part Number 1=97C5133
LOGO1 LOGO3: library part CMP-0074837-1, "IEC 61010-1 Hot Surface Warning"
LOGO2 LOGO4: library part CMP-0074835-1, "IEC 61010-1 High Voltage Warning"
Logo5: library part CMP-0074844-1
Logo6: library part CMP-0074838-1, "Texas Instrument Corporate Signature"
Logo7: library part CMP-0074847-1, "FCC_disclaimer"
Logo8: library part CMP-0074769-1
Q1: library part CMP-0000221-1, "MOSFET, N-CH, 20 V, 0.75 A, SOT-23", Alternate Manufacturer=None, Manufacturer="ON Semiconductor", Supplier Part Number 1=MGSF1N02LT1GOSCT-ND, Value1=0.1, Value2="6 nC"
R1: library part CMP-0025884-3, "RES, 0, 5%, 0.125 W, 0603", Manufacturer=Vishay/Beyschlag, Power_W=125mW, Supplier Part Number 1=MCT0603-0.0-ZZCT-ND, TempCo=ppm/C, Tolerance_%=5%, Value2=0.125W, Value_Code=0000, ValueDisplayed=0
R2: library part CMP-0016879-3, "RES, 2.05, 1%, 0.25 W, AEC-Q200 Grade 0, 1206", Manufacturer=Vishay-Dale, Power_W=250mW, Supplier Part Number 1=541-2.05FFCT-ND, TempCo="100 ppm/C", Tolerance_%=1%, Value2=0.25W, Value_Code=2R05, ValueDisplayed=2.05
R3 R4 R11 R12: library part CMP-0027002-2, "RES, 0, 5%, 0.063 W, 0402", Manufacturer=Rohm, Power_W=63mW, Supplier Part Number 1=RHM0.0JCT-ND, TempCo="500 ppm/C", Tolerance_%=5%, Value2=0.063W, Value_Code=0000, ValueDisplayed=0
R5 R14 R17: library part CMP-0026162-1, "RES, 20.0 k, 1%, 0.063 W, 0402", Manufacturer=Vishay-Dale, Power_W=63mW, Supplier Part Number 1=541-20.0KLCT-ND, TempCo="100 ppm/C", Tolerance_%=1%, Value2=0.063W, Value_Code=20k0, ValueDisplayed=20.0k
R6 R8 R9 R15: library part CMP-0026902-3, "RES, 300, 5%, 0.063 W, AEC-Q200 Grade 0, 0402", Manufacturer=Vishay-Dale, Power_W=63mW, Supplier Part Number 1=541-300JCT-ND, TempCo="200 ppm/C", Tolerance_%=5%, Value2=0.063W, Value_Code=300R, ValueDisplayed=300
R7 R16: library part CMP-0026738-1, "RES, 49.9, 1%, 0.063 W, 0402", Manufacturer="Yageo America", Power_W=63mW, Supplier Part Number 1=311-49.9LRCT-ND, TempCo="100 ppm/C", Tolerance_%=1%, Value2=0.063W, Value_Code=49R9, ValueDisplayed=49.9
R10: library part CMP-0018748-3, "RES, 0, 5%, 0.25 W, AEC-Q200 Grade 0, 1206", Manufacturer=Panasonic, Power_W=250mW, Supplier Part Number 1=P0.0ECT-ND, TempCo="600 ppm/C", Tolerance_%=5%, Value2=0.25W, Value_Code=0000, ValueDisplayed=0
R18: library part CMP-0025963-3, "RES, 10.0, 1%, 0.063 W, AEC-Q200 Grade 0, 0402", Manufacturer=Vishay-Dale, Power_W=63mW, Supplier Part Number 1=541-10.0LCT-ND, TempCo="100 ppm/C", Tolerance_%=1%, Value2=0.063W, Value_Code=10R0, ValueDisplayed=10.0
T1 T2: library part CMP-0030623-1, "Transformer, 105uH, TH", Manufacturer="Wurth Elektronik", ValueDisplayed=105uH
TH1 TH2 TH3 TH4: library part CMP-0003719-1, "Testpoint", Manufacturer="Texas Instruments", PartNumber=TP_H0.45P0.75
TP1: library part CMP-0055153-1, "Test Point, Compact, SMT", Manufacturer=Keystone, Supplier Part Number 1=36-5016TR-ND
TP2 TP8 TP9 TP10 TP11: library part CMP-0078143-2, "TEST POINT.  No entry in BOM.", Manufacturer=N/A
TP4: library part CMP-0003968-1, "Test Point, SMT", Manufacturer=Harwin, PartNumber=S2751-46R, Supplier Part Number 1=952-2664-1-ND
U1 U2: library part CMP-0088545-3, "600-V 30-m? Integrated GaN Power Stage with Smart Driver", Manufacturer="Texas Instruments", Max Supply Voltage=18V, Min Supply Voltage=7.5V, Nominal Supply Current=13mA, Operating Temperature Range="-40°C to +125°C", Output Voltage=480V
U3: library part CMP-0089510-1, Digikey Part Number=296-48140-1-ND, Manufacturer="Texas Instruments", Max Supply Voltage=5.5V, Min Supply Voltage=2.25V, Mouser Part Number=595-ISO7741FDBQR, Nominal Supply Current=0.8-18mA, Operating Temperature Range="-55°C to +125°C"
U4: library part CMP-0091060-1, "Automotive, robust EMC, six-channel, 4/2, reinforced digital isolator 16-SSOP -40 to 125", Digikey Part Number=296-ISO7762FQDBQRQ1CT-ND, Manufacturer="Texas Instruments", Max Supply Voltage=5.5V, Min Supply Voltage=2.25V, Mouser Part Number=595-ISO7762FQDBQRQ1, Nominal Supply Current=2.1-25.7mA, Operating Temperature Range="-40°C to +125°C"
U5 U6: library part CMP-0076095-1, "Low-Noise 1 A, 420 kHz Transformer Driver, DBV0006A (SOT-23-6)", Alternate Manufacturer="Texas Instruments", Alternate PartNumber=SN6505BDBVT
ZZ2: library part CMP-0077236-1
ZZ3: library part CMP-0077237-1
ZZ4: library part CMP-0077238-1

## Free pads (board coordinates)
  round 50 smd paste-30: 1(573,404.94) 1(596,223.94) 1(805,997) 1(843,1096) 1(849,1215) 1(1089,461) 1(1103,1122) 1(1143,662) 1(1164,877) 1(1535.55,1076) 1(1574,986) 1(1620,299.94) 1(1801,639.94) 1(1886,847.62) 1(1917,899) 1(1985,852.27) 1(2087,441) 1(2222,1012.44) 1(2756,456.26) 1(2778,609) 1(2836,468.19)

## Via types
v1: diameter 18, hole 8, Top Layer to Bottom Layer, tented both sides, 781 vias
v2: diameter 16, hole 8, Top Layer to Bottom Layer, tented both sides, 44 vias
v3: diameter 26, hole 16, Top Layer to Bottom Layer, tented both sides, 17 vias
v4: diameter 24, hole 12, Top Layer to Bottom Layer, tented both sides, 6 vias
v5: diameter 20, hole 10, Top Layer to Bottom Layer, tented both sides, 6 vias
v6: diameter 16, hole 8, Top Layer to Bottom Layer, 3 vias
v7: diameter 20, hole 10, Top Layer to Bottom Layer, 1 vias

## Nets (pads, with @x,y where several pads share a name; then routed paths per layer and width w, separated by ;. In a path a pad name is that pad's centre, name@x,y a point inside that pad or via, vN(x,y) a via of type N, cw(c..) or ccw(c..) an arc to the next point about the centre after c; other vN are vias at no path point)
5V: C9.1 C26.1 C33.1 C35.1 J1.10 pad.1@2778,609 T1.2 T2.2 U3.10 U3.16 U4.16 U5.2 U5.5 U6.2 U6.5 | length 4048.5
  Top Layer w12: C9.1@979,1399.14 1000.86,1399.14 1017,1383 1040,1383 ; U3.16@1034.4,1427.38 1034.4,1388.6 1040,1383 ; U3.10@1184.4,1427.38 1186,1425.77 1186,1384.1 ; v3(1483,1358.5) 1260.71,1358.5 1235.1,1384.1 1186,1384.1 ; v3(1620,1443) 1643.92,1443 1827.62,1259.3 1961.03,1259.3 2202.73,1501 2746.71,1501 2939,1308.71 2939,775 v3(2948,766) ; U4.16@2205.5,697.7 2243.09,697.7 C26.1@2263.58,677.2 ; C26.1@2264,673.9 2295.9,673.9 v7(2296,674) ; 1040,1383 1186,1383 1186,1384.1
  Top Layer w16: 460,1433.01 467.01,1426 741.74,1426 v2@750.37,1417.37 ; U5.5@750.37,1499.84 750.37,1474.63 v2(752,1473) 765.2,1473 798.46,1439.75 829.76,1439.75 879.52,1489.5 934,1489.5 945.79,1477.71 945.79,1408.35 955,1399.14 C9.1@979,1399.14 ; U6.5@2475,365.87 2475,415 ; U6.2@2475,474.13 2475,415 ; v3(2579,359) 2579,411 2575,415 2475,415 ; v3(2777,551) 2778,552 pad.1@2778,609
  MidLayer2 w12: v3(1483,1358.5) 1514.91,1358.5 1599.41,1443 v3(1620,1443)
  MidLayer2 w16: v2(751,1418) 752,1419 v2(752,1473)
  other v3: 2455,535 2485,535
5V_H: C2.1 pad.1@843,1096 R3.2 R4.1 U1.53 U3.7 | length 1079
  Top Layer w10: v4(995,1043.28) 995,1043.82 1021.68,1070.5 1169.96,1070.5 1183,1083.54 1183,1211.9 U3.7@1180.4,1214.5
  Top Layer w12: C2.1@726.75,961 726.75,987.68 711.43,1003 709.38,1003 708.38,1002 685.5,1002 681,997.5 652.92,997.5 627,1023.42 627,1061.13 636.87,1071 818,1071 pad.1@843,1096 860,1113 v4@939,1113 ; U1.53@739.41,918.35 C2.1@739.41,961.25 ; v4(944,1117) 947.7,1117 963.77,1133.07 963.77,1166.98 R4.1@944.76,1186
  MidLayer2 w16: v4(944,1117) 995,1066 v4(995,1043.28)
5V_L: C12.1 pad.1@2222,1012.44 R11.1 R12.2 U2.53 | length 991.7
  Top Layer w12: v6@1426.72,1028.38 v6(1427,1028.65) 1436.63,1028.65 1443.38,1021.91 R12.2@1443.38,1007 ; R12.2@1447.38,1007.28 1447.38,973.87 C12.1@1454.24,967 ; C12.1@1456.17,968.93 1459.76,965.34 U2.53@1459.76,914.37 ; v6(2186,1017) 2187,1016 pad.1@2200.54,1016 ; pad.1@2222,1012.44 2229.06,1019.5 R11.1@2276.75,1019.5
  MidLayer2 w12: v6(1427,1028.65) 1427.85,1028.65 1460.5,996 1592.01,996 1592.92,995.08 1609.08,995.08 1609.99,996 1719.06,996 1722.06,993 1741.94,993 1744.94,996 2057.36,996 2058.49,994.87 2163.87,994.87 v6(2186,1017)
12V: J1.9 R10.1 | length 632.4
  Top Layer w25: J1.9@2630,265 2630,310 2634.22,310 2710,385.78 2710,452.5 2664,498.5 2664,740.91 R10.1@2736,812.91
AGND: C6.2 C9.2 C14.1 C24.2 C25.2 C26.2 C33.2 C35.2 J1.11 J1.12 pad.1@2756,456.26 TP10.1 TP11.1 U3.9 U3.15 U4.9 U5.4 U5.6 U6.4 U6.6 | length 3526.8
  Top Layer w16: v2@687.5,1474 687.5,1474.38 712.97,1499.84 U5.6@712.97,1500 ; U5.4@791.77,1500.12 813,1478.89 v2(813,1467) ; C35.2@875.73,1405.71 v3(919.29,1405.71) ; C9.2@975,1450.44 978.55,1454 v5(1006,1454) 1008.83,1456.83 1008.83,1486.83 1020,1498 1049.4,1498 1059.4,1488 U3.15@1059.4,1427.38 ; C6.2@1308.38,1415.28 1308.38,1393.62 1314,1388 1498.24,1388 1544.24,1342 1637,1342 1785.98,1193.02 1994.17,1193.02 2224.16,1423 2723.37,1423 2860,1286.37 2860,755 v3(2851,746) 2851,556.5 2759,464.5 2759,294 J1.11@2730,265 ; v5(1352,1443) 1372.38,1443 C24.2@1373.38,1444 ; C25.2@1515.38,1442 1539,1418.38 v5(1539,1413) ; v3(2003,697) 2029.8,697 U4.9@2030.5,697.7 ; v3(2060,588) 2060,621.62 C14.1@2062.38,624 ; v3(2226,583) 2236,583 2260,607 C26.2@2260,626.38 ; v3(2409,395) 2409,394.46 U6.4@2437.6,365.87 ; U6.6@2512.4,365.87 2539,339.27 v3(2539,335) ; v3(2630,468) 2630,440 C33.2@2655,415
  other v2: 687.5,1469
  other v5: 1234,1432 1255,1432 1276,1432
Bot_FET_FAULT: J1.3 TP9.1 U4.12 | length 968.4
  Top Layer w10: U4.12@2105.5,697.7 2105.5,663.05 2105.05,662.6 2116.63,651.02 2122.81,651.02 2135.25,638.58 2135.25,474.88 2330,280.13 J1.3@2330,265
  MidLayer1 w10: TP9.1@2060,278 2060,340 2096.89,376.89 2295.11,376.89 2330,342 J1.3@2330,265
Bot_FET_OC: J1.5 U4.13 | length 556.8
  Top Layer w10: U4.13@2130.5,697.7 2130.5,665.25 2150.75,645 2150.75,544.25 J1.5@2430,265
Bot_FET_PWM: J1.1 pad.1@2087,441 R16.1 | length 305.2
  Top Layer w10: R16.1@2088.04,511.38 2088.04,406.96 J1.1@2230,265
Bot_FET_TEMP: J1.7 U4.14 | length 622.4
  Top Layer w10: U4.14@2155.5,697.7 2155.5,662.17 2174.25,643.42 2174.25,561.75 2413,323 2472,323 J1.7@2530,265
FAULT_H: pad.1@1103,1122 U1.48 U3.5 | length 490.2
  Top Layer w6: U1.48@867.36,918.35 868,918.98 868,1017.04 915.96,1065 962,1065 996,1099 1080,1099 pad.1@1103,1122 1103,1144 1105.26,1144 1134.4,1173.13 U3.5@1134.4,1210.5 ; U3.5@1130.4,1214.5 U3.5@1134.4,1210.5 ; U3.5@1134.4,1214.78 U3.5@1134.4,1210.5
FAULT_L: pad.1@1574,986 U2.48 U4.5 | length 857.4
  Top Layer w6: U2.48@1587.71,914.37 1587.71,972.29 pad.1@1574,986 1574,1019.89 1622.11,1068 1841.58,1068 1857.39,1052.18 1857.39,1016.35 1881.24,992.5 1955.5,992.5 2002,1039 2093.58,1039 2107.37,1025.21 2107.37,965.11 2105.5,963.24 U4.5@2105.5,910.3
HVBUS: C15.1 C16.1 C17.1 C18.1 C19.1 C20.1 C21.1 C38.1 HV.1 pad.1@573,404.94 pad.1@596,223.94 TP5.1 U1.2 U1.3 U1.4 U1.5 U1.6 U1.7 U1.8 U1.9 U1.10 U1.11 U1.12 U1.13 U1.14 U1.15 | length 557.7
  Top Layer w10: 523.11,807.01 U1.4@563,807.01 ; 524.82,730.24 U1.7@563,730.24 ; v1(527,651.06) 529.41,653.46 U1.10@563,653.46 ; 527.24,627.87 U1.11@563,627.87 ; 527.4,832.6 U1.3@563,832.6 ; 527.88,755.83 U1.6@563,755.83 ; 528.35,704.65 U1.8@563,704.65 ; 528.97,858.19 U1.2@563,858.19 ; 529.49,781.42 U1.5@563,781.42 ; 529.55,679.06 U1.9@563,679.06 ; 533.31,576.69 U1.13@563,576.69 ; 533.28,602.28 U1.12@563,602.28 ; U1.15@563,525.51 503.5,525.51 C19.1@497.74,531.28 517.57,551.1 U1.14@563,551.1
  other v1: 636,25 670,25 389.23,26 424,26 460,26 496,26 532,26 567,26 601,26 653,35 688,35 371.23,36 406,36 442,36 478,36 514,36 550,36 584,36 619,36 672,44 602,45 635,45 389.23,46 424,46 460,46 496,46 532,46 567,46 653,54 689,54 406.23,55 441,55 477,55 513,55 549,55 584,55 618,55 371,56.94 672,64 388.23,65 423,65 459,65 495,65 531,65 567,65 601,65 636,65 655,73 689,73 620,74 406.23,75 441,75 477,75 513,75 549,75 584,75 468,437 488,437 508,437 528,437 548,437 479,454 499,454 519,454 447,651.06 467,651.06 487,651.06 507,651.06 458,668.06 478,668.06 498,668.06 518,668.06 468,864.06 488,864.06 508,864.06 479,881.06 499,881.06 519,881.06
  other v2: 120,648.66 140,648.66 160,648.66 180,648.66 200,648.66 220,648.66 130,670 150,670 170,670 190,670 210,670 230,670
IN_H: C5.2 R6.2 U1.47 | length 389
  Top Layer w6: U1.47@892.95,918.35 892.95,965.2 892.95,969.86 ; C5.2@902.01,964.92 926.92,989.83 926.92,1036.92 942,1052 969,1052 1002.5,1085.5 1121.5,1085.5 1137.38,1101.38 R6.2@1155.4,1101.38
IN_L: C23.2 pad.1@1917,899 R15.2 U2.47 | length 715
  Top Layer w6: U2.47@1612.95,918.35 1612.95,972.71 1646.31,1006.07 1646.31,1046.14 1655,1054.83 1837.17,1054.83 1844,1048 1844,998 1861,981 ; pad.1@1907.47,903.28 1875.72,903.28 1861.5,917.5 1861.5,980.5 1861,981 ; R15.2@2025.38,1018 2005,1018 1968,981 1861,981
INA: U4.2
ISO_12V_H: C31.1 L4.2 R1.1 | length 135
  Top Layer w16: L4.2@720.28,1205.59 735.91,1205.59 C31.1@771.86,1169.63 ; C31.1@774,1171.77 811.73,1171.77 R1.1@833.5,1150
ISO_12V_H_B: C37.1 D2.1 L4.3 | length 555.1
  Top Layer w16: D2.1@212.8,1223.66 611.65,1223.66 629.72,1205.59 663,1172.31 663,1144.5 C37.1@702.5,1105
ISO_12V_L: C11.2 C30.1 D5.1 L3.2 R2.2 R10.2 U2.46 | length 2164.9
  Top Layer w12: R2.2@1683,1147 1683.27,1146.73 v2(1712.47,1146.73)
  Top Layer w15: U2.46@1638.89,914.37 1638.89,933.28 1659,953.39 1659,953.7 1677.07,971.77 C11.2@1677.07,1012 ; 2103.43,1113.3 2130.73,1086 2158.01,1086 2158.01,1061.79 2167.79,1052 2267,1052 2307.59,1092.59 L3.2@2307.59,1119.72 ; 2107.8,1118.33 2108.13,1118
  Top Layer w25: C11.2@1673.07,1016 1674.07,1017 v2(1732,1017) ; D5.1@2054.94,1101 2067.23,1113.3 v2(2089.7,1113.3) 2103.43,1113.3 2108.13,1118 ; 2107.8,1118.33 2300.47,1311 2699.61,1311 2764,1246.61 2764,1157 2714.96,1107.96 2714.96,948.13 R10.2@2736,927.09
  MidLayer2 w12: v2(1712.47,1146.73) 1718.27,1146.73 1795,1070
  MidLayer2 w25: v2(1732,1017) 1785.73,1070.73 ; 1795,1070 1960.7,1070 2004,1113.3 v2(2089.7,1113.3)
ISO_12V_L_B: C36.1 D3.1 L3.3 | length 151.1
  Top Layer w10: L3.3@2307.59,1210.28 2334.81,1237.5 C36.1@2367,1237.5 2378.5,1249 2436.65,1249 D3.1@2440.89,1253.24
ISO_RET_H_B: C37.2 D2.2 L4.4 | length 593.6
  Top Layer w20: D2.2@118.31,1223.66 175.97,1166 618.13,1166 629.72,1154.41 639.5,1144.63 C37.2@639.5,1105
ISO_RET_L_B: C36.2 D3.2 L3.4 | length 216.2
  Top Layer w10: L3.4@2256.41,1210.28 2258,1208.69 2258,1190 2274,1174 2367.5,1174 2368,1174.5 2390.5,1174.5 2408,1157 D3.2@2439.13,1157
ISONC2: T2.5
ISONC3: T1.5
NC1: TH1.1
NC2: TH2.1
NC3: TH3.1
NC4: TH4.1
NetC1_1: C1.1 D1.1 D6.1 R1.2 U1.46 | length 917.4
  Top Layer w12: U1.46@922.54,918.62 922.54,938.54 932.5,948.5 932.5,954.08 943.92,965.5 953.07,965.5 C1.1@953.07,971.78 ; v4(1031,1048) 1158.64,1048 1187.16,1019.48 1233.91,1019.48 1262.42,1048 D6.1@1328.47,1048 ; D1.1@1287.99,1231 1287.99,1167.01 1336,1119 1336,1068.99 D6.1@1339.47,1065.52
  Top Layer w16: C1.1@953.07,971.78 C1.1@953.07,989 ; C1.1@957.07,989.28 1017.28,989.28 1029.28,1001.28 v4@1029.28,1048
  Top Layer w20: R1.2@896.5,1150 899.5,1147 v4(935,1147) ; v4@1029.28,1048 v4(1031,1048)
  MidLayer2 w20: v4(935,1147) 961.89,1147 1032.5,1076.39 1032.5,1049.5 v4(1031,1048)
NetC6_1: C6.1 R7.2 U3.11 | length 336.1
  Top Layer w6: U3.11@1159.4,1427.38 1159.4,1463.4 1165,1469 1321.02,1469 1328.02,1462 1328.02,1438.6 1351.62,1415 1418.81,1415 R7.2@1419.38,1414.43 ; R7.2@1417.37,1422 R7.2@1418.38,1423.01
NetC8_1: C8.1 pad.1@1535.55,1076 R12.1 R14.2 R17.2 U2.52 | length 491.1
  Top Layer w6: C8.1@1483,1105.27 1483,1083 1483.62,1082.38 ; U2.52@1485,918.35 1485,1007.38 1488.62,1011 1483.62,1016 1483.62,1082.38 ; R17.2@1764.76,1116 1758.76,1110 1579,1110 1545,1076 pad.1@1535.55,1076 1529.17,1082.38 1483.62,1082.38
NetC10_1: C10.1 R4.2 U3.1 | length 91.3
  Top Layer w10: R4.2@992,1186 C10.1@992,1229 1000.56,1229 1014.79,1214.78 U3.1@1034.4,1214.78
NetC14_2: C14.2 R16.2 U4.11 | length 159.5
  Top Layer w10: U4.11@2080.5,697.7 2080.5,660.83 2080.5,650.16 C14.2@2106.66,624 ; R16.2@2088.04,558.62 2106,576.58 2106,620.38 C14.2@2108.14,622.52 ; C14.2@2112.12,626.5 C14.2@2112.12,629.21
NetC27_1: C27.1 R11.2 U4.1 | length 126.3
  Top Layer w10: U4.1@2205.5,910.3 2207.2,912 C27.1@2240.5,912 2266.75,912 2280.25,925.5 R11.2@2280.25,970.76
NetD1_2: D1.2 R2.1 | length 141.6
  Top Layer w12: D1.2@1463.01,1230 1527.47,1230 1545.83,1211.64 R2.1@1545.83,1160.5
NetD2_3: D2.3 T2.4 | length 278.6
  Top Layer w20: D2.3@118.31,987.44 118.31,1022.52 153.79,1058 334.02,1058 T2.4@343.28,1048.74
NetD2_4: D2.4 T2.6 | length 386.3
  Top Layer w15: D2.4@212.8,987.44 D2.4@219.36,994 ; D2.4@216.8,997.72 320.41,997.72 325.42,992.72 540.87,992.72 541.15,992.43 544,995.28 T2.6@544,1041.74
NetD3_3: D3.3 T1.4 | length 169.4
  Top Layer w25: T1.4@2567.24,1036.26 2678.11,1147.13 D3.3@2678.11,1159.76
NetD3_4: D3.4 T1.6 | length 414.6
  Top Layer w25: T1.6@2367.24,1036.26 2367.24,1059.24 2412,1104 2525.78,1104 2676.03,1254.24 D3.4@2678.11,1254.24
